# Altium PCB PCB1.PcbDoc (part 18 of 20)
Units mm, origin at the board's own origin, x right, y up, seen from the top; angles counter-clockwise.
Board outline 294.51 x 138.18 mm, 12 copper layers (Top Layer 1 _Signal, L2_GND, L3_Signals, L4_GND, L5_POWER, L6_Signals, L7_GND, L8_Signals, L9_GND, L10_POWER, L11_GND, Bottom Layer_Signals), stack 1.788 mm thick; 1254 components, 836 nets, 5699 pads, 2073 vias.
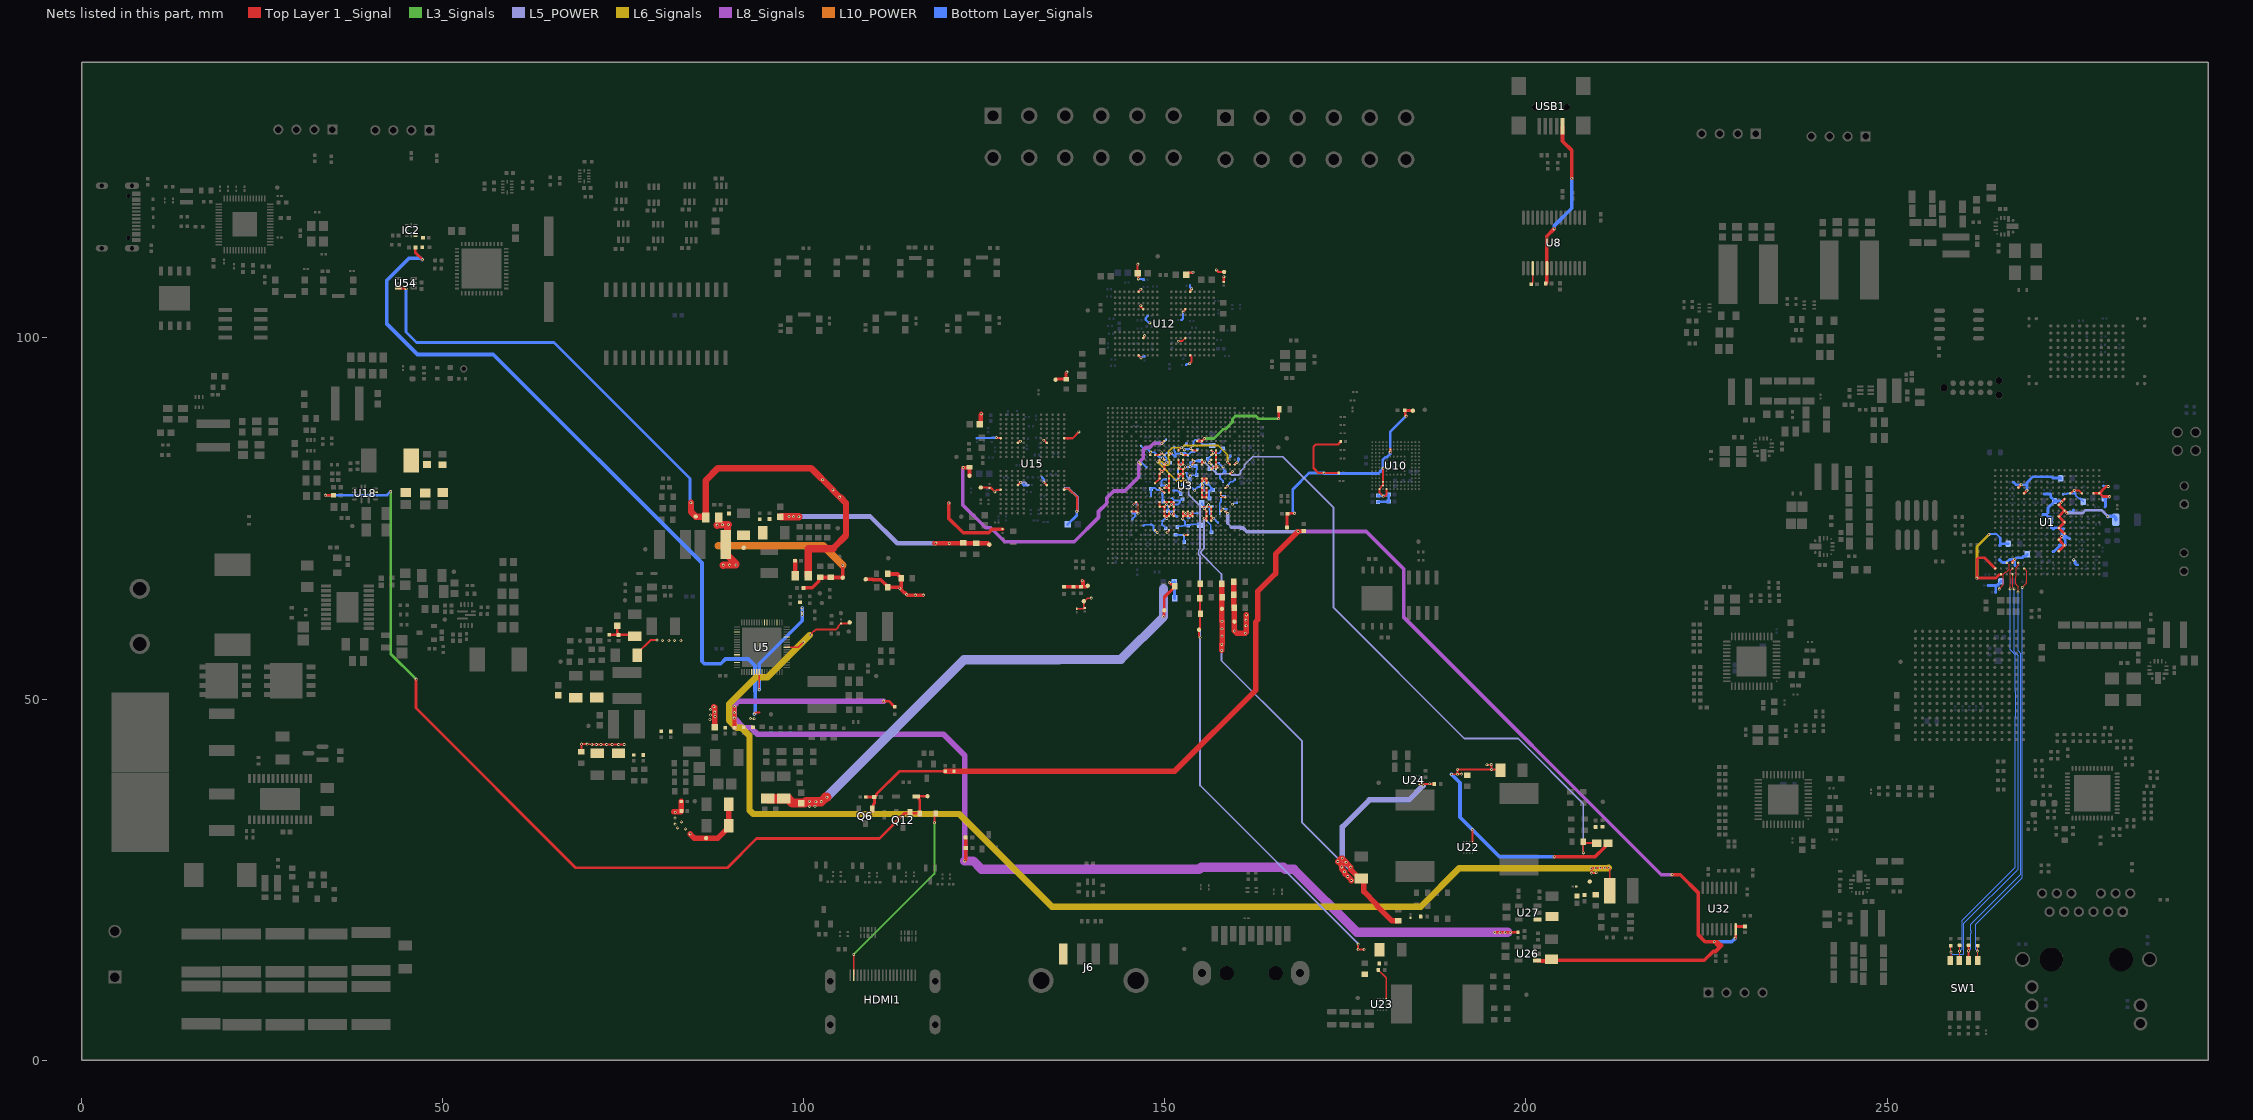
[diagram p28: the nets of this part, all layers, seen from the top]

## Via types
v1: diameter 0.4, hole 0.2, Top Layer 1 _Signal to Bottom Layer_Signals, 2009 vias
v2: diameter 0.508, hole 0.254, Top Layer 1 _Signal to Bottom Layer_Signals, 36 vias
v3: diameter 0.5, hole 0.2, Top Layer 1 _Signal to Bottom Layer_Signals, 12 vias
v4: diameter 1.27, hole 0.711, Top Layer 1 _Signal to Bottom Layer_Signals, 6 vias
v5: diameter 0.3, hole 0.2, Top Layer 1 _Signal to Bottom Layer_Signals, 5 vias
v6: diameter 0.254, hole 0.2, Top Layer 1 _Signal to Bottom Layer_Signals, 3 vias
v7: diameter 0.305, hole 0.2, Top Layer 1 _Signal to Bottom Layer_Signals, 1 vias
v8: diameter 0.254, hole 0.152, Top Layer 1 _Signal to Bottom Layer_Signals, 1 vias

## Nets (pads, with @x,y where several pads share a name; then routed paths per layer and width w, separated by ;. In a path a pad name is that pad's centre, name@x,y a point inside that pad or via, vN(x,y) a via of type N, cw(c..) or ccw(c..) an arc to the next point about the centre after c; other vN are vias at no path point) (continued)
VCC1V8_PMU_DDR_S3: C5.1 C315.1 C316.1 C317.1 C318.1 C319.1 C320.1 C322.1 C323.1 C324.1 C393.1 C394.1 C395.1 C396.1 C397.1 C398.1 C399.1 C400.1 C401.1 R30.1 R31.1 TP18.1 TP62.1 TP81.1 U3.N28 U3.R27 U12.F1 U12.F12 U12.G4 U12.G9 U12.T4 U12.T9 U12.U1 U12.U12 U15.F1 U15.F12 U15.G4 U15.G9 U15.T4 U15.T9 U15.U1 U15.U12 U54.6 | length 158.4
  Top Layer 1 _Signal w0.127: v1(147.207,100.311) v1@147.259,100.363
  Top Layer 1 _Signal w0.254: v1(151.854,99.547) 151.882,99.575 152.427,99.575 152.841,99.989 U12.T4@152.854,99.989
  Top Layer 1 _Signal w0.305: TP62.1@124.514,79.282 125.864,79.282 v1(126.463,78.683) 126.741,78.962 127.241,78.962 U15.F12@127.25,78.971 ; v1(126.67,86.192) 126.733,86.129 127.241,86.129 U15.U12@127.25,86.121 ; U15.G9@129.65,79.621 129.65,79.633 v1@130.02,80.003 ; U15.T9@129.65,85.471 129.662,85.471 129.879,85.688 v1(129.99,85.688) ; v1@130.012,80.033 v1(130.031,80.015) v1@130.02,80.004 ; v1(133.232,85.838) 133.25,85.82 133.301,85.82 U15.T4@133.65,85.471 ; v1(133.259,80.03) 133.259,80.021 133.65,79.63 U15.G4@133.65,79.621 ; U15.U1@136.05,86.121 137.229,86.121 v1(138.091,86.983) ; U15.F1@136.062,78.971 136.226,79.134 136.663,79.134 137.867,77.93 137.867,76.215 137.835,76.182 137.835,75.979 v1(137.817,75.961) ; v1(146.26,110.221) 146.26,110.196 146.229,110.164 146.229,108.931 C316.1@146.22,108.922 146.304,108.837 146.304,108.19 v1(146.322,108.172) ; U12.F1@146.354,97.589 146.354,97.577 v1(146.694,97.237) ; U12.F12@146.354,106.389 146.354,106.401 146.68,106.727 v1(146.68,106.745) ; v1(146.675,104.454) 146.675,104.331 147.004,104.001 U12.G9@147.004,103.989 ; U12.G4@147.004,99.989 147.004,100.001 147.144,100.141 147.144,100.223 147.207,100.285 v1(147.207,100.311) ; v1(152.52,103.585) 152.52,103.611 152.799,103.89 152.799,103.989 U12.T9@152.854,103.989 ; C315.1@152.941,108.747 153.233,109.039 153.848,109.039 v1(153.899,109.089) ; v1(153.417,96.425) 153.417,96.45 153.705,96.738 153.705,97.388 U12.U1@153.504,97.589 ; U12.U12@153.504,106.389 153.504,106.58 v1(153.716,106.792) ; v1(157.113,109.426) 157.138,109.426 157.43,109.134 TP81.1@158.201,109.134 ; C322.1@158.155,107.763 158.155,108.446 v1(158.174,108.465) ; U3.R27@159.029,81.178 159.029,81.182 159.349,81.502 159.349,81.52 v1(159.354,81.526) v1@159.354,81.582 ; U3.N28@159.679,82.478 159.683,82.478 159.967,82.761 v1(159.986,82.761)
  Top Layer 1 _Signal w0.381: U54.6@43.815,106.909 44.668,106.909 44.76,106.818 v1(44.924,106.818)
  Top Layer 1 _Signal w0.508: v1(120.092,77.141) 120.092,74.994 122.07,73.016 125.597,73.016 126.111,73.53 C401.1@127.508,73.53
  Top Layer 1 _Signal w0.635: C393.1@124.349,88.018 124.482,88.151 124.482,89.37 v1(124.591,89.479)
  Top Layer 1 _Signal w0.889: v1(84.38,77.182) 84.38,75.913 TP18.1@85.031,75.262 86.349,75.262 86.409,75.202 R31.1@86.409,75.116 86.409,80.26 88.126,81.977 101.001,81.977 104.022,78.956 v1(104.027,78.956) 104.027,78.906 v1(104.982,77.951) ; 104.078,70.871 105.851,72.645 105.851,77.127 v1@105.005,77.974
  Top Layer 1 _Signal w1.016: R30.1@100.622,67.063 100.622,67.232 100.626,67.236 100.626,70.818 104.024,70.818 104.078,70.871
  L5_POWER w0.305: v1(130.031,80.015) 130.049,79.997 130.638,79.997 131.024,79.61 ; v1@159.961,82.761 v1(159.986,82.761)
  L5_POWER w0.381: 136.007,79.041 136.138,79.172 136.684,79.172 137.906,77.95 137.906,76.199 137.821,76.114 137.821,75.964 v1(137.817,75.961)
  Bottom Layer_Signals w0.254: v1(146.694,97.237) 146.734,97.237 146.89,97.393 147.157,97.393 C324.1@147.17,97.406
  Bottom Layer_Signals w0.305: C398.1@123.965,86.114 123.993,86.142 124.952,86.142 124.962,86.132 C397.1@124.967,86.132 124.986,86.151 C399.1@126.034,86.151 ; C399.1@126.026,86.142 126.057,86.174 126.652,86.174 v1(126.67,86.192) ; v1(130.031,80.015) 130.057,80.015 130.466,79.605 131.064,79.605 C400.1@131.083,79.624 ; C396.1@133.009,80.685 133.241,80.454 133.241,80.049 v1(133.259,80.03) ; v1(146.322,108.172) 146.331,108.163 146.979,108.163 C323.1@147.077,108.066 ; C318.1@147.624,103.027 147.365,102.768 147.365,102.515 147.787,102.093 147.908,102.093 v1(147.926,102.075) ; C319.1@152.322,102.479 152.52,102.677 v1(152.52,103.585) ; C317.1@152.924,96.255 153.076,96.407 153.399,96.407 v1(153.417,96.425) ; C320.1@153.493,107.235 153.493,107.04 153.716,106.818 v1(153.716,106.792) ; v1(159.986,82.761) 159.986,82.787 160.174,82.974 160.174,83.259 C5.1@160.195,83.28
  Bottom Layer_Signals w0.381: v1(44.924,106.818) 44.924,100.828 46.377,99.376 65.401,99.376 84.261,80.516 84.261,77.306 84.38,77.187 v1(84.38,77.182) ; C394.1@136.545,74.178 137.814,75.447 137.814,75.957 v1(137.817,75.961)
  other v1: 102.614,80.365
VCC3V3_FT232: C545.1 U8.17 | length 2.3
  Top Layer 1 _Signal w0.254: C545.1@200.737,107.448 200.941,107.652 U8.17@200.941,109.664
VCC3V3_LCD: 6.2 U27.1
VCC5V0_FT232: C541.1 U8.20 USB1.1 | length 23.8
  Top Layer 1 _Signal w0.508: C541.1@202.752,107.534 202.891,107.673 U8.20@202.891,109.664 202.891,114.091 v1(203.899,115.098) ; USB1.1@205.058,129.303 205.058,127.244 206.364,125.937 206.364,122.119 v1(206.349,122.104)
  Bottom Layer_Signals w0.508: v1(203.899,115.098) 203.899,115.504 206.349,117.954 v1(206.349,122.104)
VCC5V0_USB20_HOST: J6.1
VCC5V_HDMI_TX0: D4.1 HDMI1.18 | length 27.1
  Top Layer 1 _Signal w0.254: HDMI1.18@106.925,11.745 v1(106.925,14.632) ; v1(118.082,32.866) 118.082,33.447 118.101,33.467 118.101,33.942 D4.1@118.289,34.13
  L3_Signals w0.254: v1(106.925,14.632) 118.082,25.789 v1(118.082,32.866)
VCC14: C176.2 C517.2 C518.1 C519.1 L22.2 R125.1 TP38.1 TP76.1 U5.9 | length 174.2
  Top Layer 1 _Signal w0.254: U5.9@97.644,57.17 99.225,57.17 v1(99.937,57.883) ; v1@100.892,58.837 101.137,59.083 101.137,59.176 101.378,59.417 101.472,59.417 101.684,59.629 104.478,59.629 104.784,59.935 104.784,60.097 105.156,60.469 C176.2@105.166,60.469 106.12,60.469 106.261,60.61 TP38.1@106.354,60.61 ; v1(209.718,25.938) 209.699,25.919 209.101,25.919 v1(209.082,25.9) 209.061,25.921 209.061,26.55 v1(209.039,26.571) 209.053,26.585 209.639,26.585 v1(209.653,26.598) 209.67,26.615 210.257,26.615 v1(210.274,26.633) 210.276,26.635 210.893,26.635 v1(210.895,26.637) 210.902,26.643 211.479,26.643 v1(211.485,26.65) 211.485,26.611 211.609,26.488 L22.2@211.609,23.452
  L6_Signals w0.889: v1@100.822,58.865 99.888,57.931 94.979,53.022 93.392,53.022 89.643,49.273 89.643,47.063 90.711,45.995 91.419,45.995 92.487,44.928 92.487,34.594 93.008,34.074 121.543,34.074 134.365,21.252 185.431,21.252 190.768,26.589 209.039,26.589 209.653,26.589 210.274,26.589 210.895,26.589 211.424,26.589 v1(211.485,26.65)
  other v1: 100.92,58.865
VCC_1V8_S0: C15.1 C32.1 C34.1 C203.1 C466.1 C467.1 C468.1 C556.2 C632.1 R100.2 R102.2 R133.2 R253.2 U3.AA7 U3.AC6 U3.AC7 U3.AC25 U3.H20 U3.H21 U3.W25 U3.Y26 U5.58 | length 189.9
  Top Layer 1 _Signal w0.152: U3.AA7@146.029,77.278 146.349,76.958 146.349,75.852 146.288,75.79 v1(146.288,75.723)
  Top Layer 1 _Signal w0.254: U3.AC6@145.379,75.978 146.033,75.978 v1(146.288,75.723) ; v5(145.676,76.939) 145.683,76.939 146.022,77.278 U3.AA7@146.029,77.278 ; U3.AC25@157.729,75.978 157.729,75.996 158.021,76.288 158.021,76.293 v1(158.025,76.297) ; U3.W25@157.729,78.578 157.742,78.565 157.742,78.049 v1(157.752,78.04) 157.791,78.04 157.89,77.941 158.367,77.941 U3.Y26@158.379,77.928
  Top Layer 1 _Signal w0.381: v1@111,49.632 111.071,49.702 v1(111.071,49.708) 111.075,49.704 111.79,49.704 112.526,48.968 112.526,48.849 C467.1@112.586,48.908 ; U3.H20@154.479,85.728 U3.H21@155.129,85.728 155.462,86.061 v1(155.462,86.064) v1@155.471,86.072 ; v1(165.756,88.821) 165.76,88.825 165.76,90.022 R253.2@165.835,90.097 ; v1(195.675,17.693) v1(196.432,17.693) v1(197.123,17.693) v1(197.839,17.693) R133.2@198.883,17.693
  Top Layer 1 _Signal w0.508: v1(90.4,48.938) 90.412,48.926 C556.2@90.412,46.032 ; v1(122.268,27.584) 122.419,27.735 R100.2@122.419,30.84
  L3_Signals w0.381: v1(155.462,86.064) 156.777,86.064 158.06,87.347 158.365,87.347 159.35,88.332 159.35,88.761 159.761,89.173 162.58,89.173 162.932,88.821 v1(165.756,88.821)
  L8_Signals w0.762: v1(111.071,49.708) 90.968,49.708 90.372,49.111 v1(90.372,47.364) 91.748,45.988 92.709,45.988 93.575,45.122 104.697,45.122 104.712,45.136 105.262,45.136 105.277,45.122 119.342,45.122 122.29,42.174 122.29,27.606 v1(122.268,27.584)
  L8_Signals w1.27: v1(122.268,27.584) 123.446,27.584 124.601,26.43 154.757,26.43 155.031,26.704 166.406,26.704 166.68,26.43 167.868,26.43 176.605,17.693 v1(195.675,17.693) v1(196.432,17.693) v1(197.123,17.693) 197.488,17.693
  Bottom Layer_Signals w0.254: C203.1@145.508,74.907 145.508,74.952 145.872,75.316 145.872,75.566 146.028,75.723 v1(146.288,75.723) ; C32.1@145.525,75.724 145.525,75.747 145.53,75.751 v1@146.26,75.751 ; v5(145.676,76.939) 145.689,76.939 145.811,77.061 146.073,77.061 146.11,77.024 146.11,77.012 146.221,76.901 C632.1@146.267,76.901 ; C34.1@157.597,75.656 157.598,75.923 ; v1(158.025,76.297) 158.04,76.282 158.517,76.282 158.53,76.269 C466.1@158.53,76.267 158.53,76.277 158.517,76.29 158.404,76.29 158.368,76.326 158.094,76.326 158.091,76.324 157.998,76.324 157.998,76.31 157.913,76.224 157.899,76.224 157.598,75.923 ; C15.1@158.263,78.135 158.259,78.139 157.89,78.139 157.791,78.04 v1(157.752,78.04) 157.752,77.27 157.598,77.116 157.598,75.923 ; v1(159.354,76.976) 159.394,76.976 159.521,77.103 160.003,77.103 160.007,77.107 C468.1@160.007,77.153
  other v1: 90.39,48.116
VCC_1V8_S3_PLDO6: C174.1 R30.2 U5.20 | length 2.1
  Top Layer 1 _Signal w0.635: C174.1@98.8,69.141 98.818,69.123 R30.2@98.818,67.063
VCC_2V0_PLD0_S3: C637.1 R292.2 R293.2
VCC_2V0_PLDO_S3: C553.1 C554.1 U5.13 U5.59 | length 16.2
  Top Layer 1 _Signal w0.254: v1(93.838,51.3) 93.844,51.305 93.844,53.72 U5.59@93.849,53.725
  Bottom Layer_Signals w0.508: v1(93.838,51.3) 93.838,54.885 99.791,60.837 99.791,61.617 v1(99.795,61.621) 99.795,62.073 v1(99.793,62.075) 99.774,62.094 v1(99.774,62.611)
VCC_3V3_S0: 5.2 C204.1 C547.1 J5.2 Q6.1 R107.1 R113.1 R114.1 R119.2 U3.AC26 U26.1 U32.16 | length 223.1
  Top Layer 1 _Signal w0.254: U3.AC26@158.379,75.978 v1(158.69,75.668)
  Top Layer 1 _Signal w0.381: R107.1@108.564,36.447 108.577,36.434 109.771,36.434 R119.2@109.785,36.42 ; Q6.1@109.495,34.767 109.63,34.901 109.63,35.408 109.785,35.563 R119.2@109.785,36.42 ; R113.1@119.593,39.996 113.235,39.996 110.06,36.82 110.06,36.674 109.806,36.42 R119.2@109.785,36.42 ; v1(228.965,16.884) 228.965,16.889 229.067,16.99 229.067,17.392 229.062,17.397 U32.16@229.062,17.435 ; U32.16@229.062,18.497 C547.1@230.328,18.497
  Top Layer 1 _Signal w0.508: v1(168.454,73.196) 168.492,73.234 169.216,73.234 J5.2@169.237,73.255 ; U26.1@201.553,13.791 201.599,13.745 202.09,13.745 202.123,13.711 203.31,13.711 5.2@203.551,13.953 203.38,13.953 5.2@203.036,13.609 ; 5.2@203.676,13.828 224.706,13.828 225.926,15.047 226.264,15.047 227.077,15.861 ; v1(220.245,25.67) 221.359,25.67 223.88,23.149 223.88,17.308 224.807,16.381 226.077,16.381 226.598,15.861 227.077,15.861 ; v1(226.081,16.385) 226.559,16.385 227.077,15.866 227.077,15.861
  Top Layer 1 _Signal w0.762: R113.1@119.593,39.996 120.813,39.996 151.359,39.996 162.552,51.189 162.552,60.66 162.857,60.966 162.857,64.912 165.325,67.38 165.325,70.067 v1(168.454,73.196)
  L5_POWER w0.254: 158.69,74.323 159.207,73.805
  L5_POWER w0.508: 158.69,74.323 v1(158.69,75.668) ; 159.207,73.805 160.419,73.805 160.532,73.692 160.819,73.692 161.346,73.165 168.205,73.165 168.236,73.196 v1(168.454,73.196)
  L8_Signals w0.508: v1(168.454,73.196) 177.872,73.196 183.102,67.966 183.102,61.288 218.72,25.67 v1(220.245,25.67)
  Bottom Layer_Signals w0.254: C204.1@158.681,74.754 158.685,74.758 158.685,75.664 v1(158.69,75.668)
  Bottom Layer_Signals w0.508: v1(226.081,16.385) 228.513,16.385 v1@228.965,16.837
VCC_5V0: C196.2 C197.2 C440.1 C441.1 C443.1 D4.2 D7.1 L16.2 Q12.1 R77.1 TP20.1 U18.5 | length 128.2
  Top Layer 1 _Signal w0.381: v1(33.748,78.224) 33.75,78.227 R77.1@34.877,78.227 ; v1(46.31,52.746) 46.31,48.741 68.426,26.625 89.4,26.625 93.469,30.693 110.461,30.693 113.956,34.188 116.001,34.188 D4.2@116.059,34.13 116.059,36.029 115.909,36.18 115.909,36.43 115.824,36.514 D7.1@115.574,36.514 115.59,36.53 117.127,36.53 TP20.1@117.143,36.546
  L3_Signals w0.381: v1(42.804,78.717) 42.804,56.251 v1(46.31,52.746)
  Bottom Layer_Signals w0.381: v1(33.748,78.224) 42.311,78.224 v1(42.804,78.717)
VCCA_1V8: C16.2 C305.2 C310.2 C455.2 C461.1 C462.2 C555.2 C683.1 C685.1 IC2.1 R128.2 R130.1 R273.1 TP61.1 U3.AG11 U3.AG14 U3.AH18 U3.K16 U3.M12 U3.N27 U3.U18 U5.60 | length 133.2
  Top Layer 1 _Signal w0.254: v1(93.145,47.916) 93.377,48.148 93.878,48.148 ; C16.2@137.804,62.509 138.774,62.509 138.885,62.62 C305.2@138.885,62.646 ; C305.2@138.908,62.633 138.898,62.633 C305.2@138.885,62.646 ; v1(139.808,63.981) 139.78,63.953 139.284,63.953 138.871,63.54 TP61.1@138.778,63.54 138.778,62.763 138.885,62.656 C305.2@138.885,62.646 ; U3.AG11@148.629,73.378 v1(148.94,73.067) ; v1(149.015,82.834) 149.015,82.864 U3.M12@149.279,83.128 ; v1(150.305,73.083) 150.305,73.085 150.579,73.36 U3.AG14@150.579,73.378 ; U3.K16@151.879,84.428 152.243,84.792 v1(152.297,84.792) v1@152.297,84.777 ; v1(152.66,72.728) U3.AH18@153.179,72.728 ; v1(152.895,80.17) 152.895,80.166 153.179,79.882 U3.U18@153.179,79.878 ; v1@158.677,82.803 v1(158.682,82.803) 158.686,82.803 159.011,82.478 U3.N27@159.029,82.478
  Top Layer 1 _Signal w0.381: R273.1@46.203,112.527 46.203,111.828 v1(47.188,110.843)
  L6_Signals w0.254: v1(152.895,80.17) 151.68,80.17 149.016,82.834 149.043,82.862 149.591,82.862 150.081,82.372 150.425,82.372 150.665,82.612 150.665,83.09 150.484,83.271 150.484,84.24 151.036,84.792 152.337,84.792 152.65,85.104 157.396,85.104 158.672,83.828 158.672,82.812 v1(158.682,82.803)
  Bottom Layer_Signals w0.254: C310.2@147.065,74.022 147.075,74.022 147.19,74.138 C462.2@148.087,74.138 148.1,74.125 148.268,74.125 148.418,73.974 148.418,73.443 148.766,73.095 148.912,73.095 v1(148.94,73.067) ; R128.2@151.489,72.747 152.048,72.747 152.077,72.719 152.651,72.719 v1(152.66,72.728) 152.667,72.721 152.667,71.754 R130.1@152.673,71.747 ; v1(152.297,84.792) 152.325,84.819 152.408,84.819 152.95,85.362 C461.1@152.996,85.362 ; v1(158.682,82.803) 158.71,82.831 158.71,83.226 159.086,83.602 C455.2@159.086,83.648
  Bottom Layer_Signals w0.508: v1(47.188,110.843) 46.974,111.056 45.359,111.056 42.234,107.93 42.234,102.002 46.522,97.713 57.012,97.713 85.899,68.826 85.899,55.214 86.214,54.899 88.51,54.899 89.148,55.537 92.311,55.537 93.247,54.601 93.247,51.054 93.301,51 93.301,48.072 v1(93.145,47.916)
  other v1: 93.115,47.273 92.599,47.288
VCCQ: C63.1 C64.1 C210.2 C211.2 C212.1 C213.2 C214.2 C215.2 L4.1 R31.2 R41.2 R65.1 R66.2 R67.1 R172.2 TP39.1 TP43.1 TP45.1 U3.V26 U5.25 U10.C6 U10.M4 U10.N4 U10.P3 U10.P5 | length 90
  Top Layer 1 _Signal w0.203: U10.P3@179.704,79.07 U10.N4@180.204,79.57
  Top Layer 1 _Signal w0.254: U3.V26@158.379,79.228 158.379,79.245 158.384,79.241 158.41,79.241 158.649,79.48 v1(158.655,79.48)
  Top Layer 1 _Signal w0.305: R67.1@174.064,81.322 174.064,81.302 174.042,81.279 171.281,81.279 170.579,81.982 170.579,84.926 170.896,85.243 173.968,85.243 174.316,85.592 174.341,85.592 174.364,85.614 R65.1@174.364,85.639 ; U10.P3@179.704,79.07 179.704,78.612 v1(180.23,78.085) 180.248,78.104 180.518,78.104 180.704,78.289 U10.P5@180.704,79.07 ; U10.N4@180.204,79.57 U10.M4@180.204,80.07 180.204,80.989 180.222,81.007 v1(180.222,81.952)
  Top Layer 1 _Signal w0.381: TP45.1@166.915,73.748 166.915,75.379 167.252,75.717 v1(167.961,75.717) ; R66.2@166.975,75.652 R66.2@167.252,75.652 ; v1(181.195,84.181) 181.199,84.184 181.199,84.565 U10.C6@181.204,84.57 ; v1(183.416,89.176) 183.416,89.181 183.275,89.321 183.275,89.901 C212.1@183.216,89.96 183.236,89.941 184.318,89.941 TP43.1@184.338,89.921
  Top Layer 1 _Signal w0.508: R41.2@99.957,65.403 101.163,65.403 102.081,66.321 102.081,66.712 102.202,66.833 105.347,66.833 105.378,66.802 TP39.1@105.403,66.802 v1(105.403,68.51)
  Top Layer 1 _Signal w1.016: v1(87.989,74.081) 88.045,74.137 v1(88.735,74.137) 88.767,74.169 v1(89.553,74.169) 89.449,74.066 89.449,71.647 L4.1@89.207,71.405 89.207,70.155 90.62,68.742 v1(90.62,68.554) 89.746,68.554 v1(89.738,68.546) 88.863,68.546 v1(88.855,68.538)
  L10_POWER w1.016: 88.122,71.223 102.69,71.223 v1(105.403,68.51)
  Bottom Layer_Signals w0.203: v1(158.655,79.48) 158.693,79.517 158.693,79.629 159.122,80.059 159.382,80.059 159.513,80.19 159.513,80.202 159.695,80.384 C215.2@159.695,80.394
  Bottom Layer_Signals w0.305: C211.2@179.539,78.155 179.59,78.104 180.212,78.104 v1(180.23,78.085) 180.256,78.085 180.349,78.179 180.893,78.179 C213.2@181.011,78.296
  Bottom Layer_Signals w0.381: v1(167.961,75.717) 167.961,75.722 167.711,75.972 167.711,79.017 169.982,81.287 v1(172.048,81.287) 172.054,81.287 172.127,81.214 179.599,81.214 179.868,81.484 179.868,81.593 180.222,81.946 v1(180.222,81.952) 180.218,81.955 180.218,82.329 180.197,82.35 180.197,83.164 180.524,83.491 180.775,83.491 181.191,83.908 181.191,84.177 v1(181.195,84.181) 181.195,87.001 183.37,89.176 v1(183.416,89.176) ; C214.2@179.525,77.284 179.562,77.32 180.966,77.32 C210.2@181.002,77.357 181.007,77.361 181.007,78.292 C213.2@181.011,78.296
VCORE0: R16.2 SW1.1 U1.P18 | length 58.3
  Top Layer 1 _Signal w0.132: SW1.1@262.551,13.773 262.547,13.777 v1(262.547,15.086) 262.559,15.098 262.559,15.85 R16.2@262.571,15.862 ; v1(268.717,65.455) 269.371,66.109 269.371,67.69 U1.P18@268.981,68.08
  Bottom Layer_Signals w0.132: v1(262.547,15.086) 262.262,15.371 262.262,18.827 268.717,25.282 v1(268.717,65.455)
VCORE1: R17.2 SW1.2 U1.R17 | length 59.3
  Top Layer 1 _Signal w0.132: v1(268.137,64.803) 268.137,65.56 267.866,65.831 267.866,65.864 267.801,65.929 267.801,66.943 267.866,67.009 267.866,68.21 268.173,68.517 268.173,68.872 U1.R17@268.181,68.88
  Top Layer 1 _Signal w0.305: SW1.2@261.281,13.773 v1(261.281,15.113) 261.285,15.116 261.285,15.882 R17.2@261.289,15.885
  Bottom Layer_Signals w0.132: v1(261.281,15.113) 261.601,15.432 261.601,17.533 261.633,17.565 261.633,17.855 261.601,17.887 261.601,18.832 268.501,25.733 268.501,56.294 268.137,56.658 v1(268.137,64.803)
VCORE2: R18.2 SW1.3 U1.T18 | length 58.8
  Top Layer 1 _Signal w0.132: SW1.3@260.011,13.773 260.036,13.797 v1(260.036,15.072) 260.039,15.074 260.039,15.883 R18.2@260.041,15.885 ; v1(267.052,65.253) 267.052,67.751 U1.T18@267.381,68.08
  Bottom Layer_Signals w0.132: v1(260.036,15.072) 260.386,15.421 260.386,19.361 267.735,26.71 267.735,47.643 267.789,47.697 267.789,51.024 267.735,51.078 267.735,56.108 267.052,56.792 v1(267.052,65.253)
VCORE3: R19.2 SW1.4 U1.T19 | length 60.1
  Top Layer 1 _Signal w0.132: SW1.4@258.741,13.773 258.858,13.89 v1(258.858,14.965) 258.838,14.985 258.838,15.83 R19.2@258.818,15.85 ; U1.T19@267.381,67.28 267.381,65.475 v1(267.598,65.257)
  Bottom Layer_Signals w0.132: v1(258.858,14.965) 258.909,14.914 258.909,14.781 259.018,14.672 260.545,14.672 260.622,14.749 260.622,18.921 268.145,26.444 268.145,56.004 267.598,56.55 v1(267.598,65.257)
VDD2_DDR_CKE: C295.2 C299.2 R264.1 TP56.1 U3.H13 U3.N8 | length 48.6
  Top Layer 1 _Signal w0.203: v1@146.39,82.755 v1(146.41,82.775) 146.414,82.775 146.679,82.51 U3.N8@146.679,82.478 ; v1@149.443,85.403 v1(149.582,85.403) 149.597,85.403 149.922,85.728 U3.H13@149.929,85.728
  Top Layer 1 _Signal w0.508: v1(122.077,82.039) 122.048,82.01 R264.1@122.852,82.01 ; R264.1@122.927,82.085 R264.1@122.852,82.01 ; TP56.1@122.957,80.905 122.942,80.92 122.942,82.01 R264.1@122.852,82.01
  L8_Signals w0.508: v1(122.077,82.039) 122.026,81.988 122.026,76.87 125.182,73.713 125.893,73.713 127.832,71.775 137.446,71.775 140.82,75.149 140.82,75.965 141.945,77.089 141.945,77.845 142.272,78.171 142.296,78.171 142.936,78.811 144.445,78.811 146.379,80.745 v1@146.379,82.744 ; v1(146.41,82.775) 146.541,82.906 146.577,82.906 146.995,83.325 146.995,84.534 147.292,84.832 147.9,84.832 148.472,85.403 v1(149.582,85.403)
  Bottom Layer_Signals w0.203: v1(146.41,82.775) 146.718,82.775 147.348,82.145 147.433,82.145 147.433,82.135 C299.2@147.471,82.096 ; v1(149.582,85.403) 149.619,85.441 149.752,85.441 149.921,85.609 149.921,85.694 150.128,85.902 C295.2@150.128,85.912
VDD_CPU_BIG0_S0: C38.1 C260.2 C261.1 C271.2 C272.2 C273.1 C274.1 C276.1 C277.2 C278.2 C279.1 C280.1 C506.1 C507.1 R121.1 R308.2 TP54.1 U3.M16 U3.M17 U3.M19 U3.N16 U3.N17 U3.N19 U3.P16 U3.P17 U3.R16 U3.R17 U3.T16 U3.T17 U23.A4 | length 105.6
  Top Layer 1 _Signal w0.254: U3.T16@151.879,80.528 U3.R16@151.879,81.178 U3.R17@152.529,81.178 ; U3.M16@151.879,83.128 U3.N16@151.879,82.478 U3.N17@152.529,82.478 152.529,83.11 152.511,83.128 U3.M17@152.529,83.128 ; v1(151.996,82.144) 151.892,82.04 151.892,81.841 U3.P16@151.879,81.828 U3.P17@152.529,81.828 ; U3.T17@152.529,80.528 U3.R17@152.529,81.178 ; v1(152.855,82.137) 152.547,81.828 U3.P17@152.529,81.828 ; U3.N19@153.829,82.478 153.829,82.496 153.988,82.655 153.988,82.895 v1(154.016,82.923) 154.016,82.932 153.829,83.119 U3.M19@153.829,83.128 ; v1(154.876,58.499) 154.876,58.539 154.732,58.683 154.732,59.454 154.869,59.591 154.889,59.591 C38.1@154.889,65.947 ; v1(176.76,16.052) 176.757,16.049 176.757,15.308 v1(176.753,15.304) 176.757,15.301 177.588,15.301 v1(177.591,15.298) 177.597,15.298 177.61,15.285 v1@177.623,15.285 ; C507.1@179.558,12.503 179.558,12.478 180.653,11.384 U23.A4@180.653,8.514 ; U3.R17@152.529,81.178 U3.P17@152.529,81.828
  L5_POWER w0.254: v1(153.517,80.863) 153.255,80.601 153.255,80.39 153.305,80.34 153.305,78.284 154.876,76.713 154.876,70.785 154.688,70.597 154.688,69.977 154.876,69.789 v1(154.876,58.499) 154.876,38.027 v1@176.805,16.098
  Bottom Layer_Signals w0.254: C278.2@151.283,80.401 151.296,80.388 151.531,80.388 151.599,80.32 152.123,80.844 v5(152.123,80.875) ; C260.2@151.836,81.308 151.836,81.945 151.968,82.077 151.968,82.116 v1@152.024,82.172 ; v1(151.996,82.144) 151.996,82.172 152.296,82.472 152.296,82.616 152.3,82.62 C279.1@152.346,82.62 ; v1(152.855,82.137) 152.867,82.149 153.478,82.149 v1(153.49,82.161) ; C261.1@152.992,81.327 153.038,81.327 153.042,81.323 153.042,80.836 153.097,80.781 153.097,80.767 153.507,80.357 153.58,80.284 C280.1@153.58,80.238 ; C280.1@153.56,80.41 153.56,80.78 153.517,80.823 v1(153.517,80.863) 153.556,80.863 153.679,80.985 154.343,80.985 C276.1@154.343,81.02 ; 154.342,81.49 154.342,81.67 154.469,81.797 C271.2@154.469,82.168 ; 154.343,81.49 154.343,81.104 C276.1@154.422,81.025 ; C271.2@154.386,82.168 154.37,82.168 C271.2@154.274,82.264 154.199,82.189 153.518,82.189 v1(153.49,82.161) ; C276.1@154.422,81.064 C276.1@154.442,81.044 ; C272.2@154.795,83.01 154.736,82.951 154.044,82.951 v1(154.016,82.923) 153.977,82.923 153.847,82.792 153.538,82.792 153.525,82.779 C277.2@153.525,82.77 153.512,82.757 153.512,82.183 v1(153.49,82.161)
VDD_CPU_BIG1_MEM_S0: C508.1 FB9.2 U3.M21 U3.N21 | length 94.2
  Top Layer 1 _Signal w0.254: U3.N21@155.129,82.478 U3.M21@155.129,83.128 ; U3.N21@155.152,82.478 155.145,82.485 155.145,82.505 155.453,82.813 v1(155.453,82.825) ; v1(207.943,28.69) 207.932,28.701 207.932,30.251 C508.1@207.922,30.262 208.138,30.046 FB9.2@209.811,30.046
  L5_POWER w0.254: v1(155.453,82.825) 156.334,81.944 156.41,81.944 157.174,81.18 158.007,81.18 158.026,81.199 159.038,81.199 159.232,81.005 160.244,81.005 160.485,81.245 160.485,81.576 161.029,82.12 161.029,82.416 162.167,83.554 166.307,83.554 173.372,76.489 173.372,62.626 191.467,44.532 198.929,44.532 207.943,35.518 v1(207.943,28.69)
VDD_CPU_BIG1_S0: C37.1 C251.2 C252.2 C253.1 C254.1 C255.1 C256.2 C257.2 C258.1 C259.1 C498.1 C499.1 FB9.1 R120.1 R307.2 TP52.1 U3.K23 U3.K24 U3.L23 U3.L24 U3.M23 U3.M24 U3.N23 U3.N24 U3.P23 U3.P24 U22.A4 | length 68.2
  Top Layer 1 _Signal w0.254: U3.P23@156.429,81.828 156.447,81.828 156.706,82.087 156.792,82.087 v1(156.82,82.115) ; U3.N23@156.429,82.478 156.412,82.478 156.164,82.726 v1(156.147,82.726) 156.147,82.846 U3.M23@156.429,83.128 ; U3.L23@156.429,83.778 156.429,83.796 156.696,84.063 v1(156.696,84.083) 156.696,84.143 156.429,84.41 U3.K23@156.429,84.428 ; U3.P24@157.079,81.828 U3.N24@157.079,82.478 ; U3.K24@157.079,84.428 U3.L24@157.079,83.778 U3.M24@157.079,83.128 U3.N24@157.079,82.478 ; v1(157.365,82.136) 157.365,82.174 157.079,82.46 U3.N24@157.079,82.478 ; v1(189.701,39.584) 190.496,39.584 190.515,39.604 190.525,39.594 191.051,39.594 v1(191.06,39.604) ; v1(190.515,39.584) v1(190.515,40.257) v1(195.241,40.257) ; v1(192.572,31.926) 192.598,31.899 U22.A4@192.598,30.261 ; v1(194.6,40.899) 194.607,40.906 195.196,40.906 v1(195.202,40.912) 195.222,40.893 195.222,40.277 v1(195.241,40.257) ; R307.2@196.475,40.145 196.363,40.257 v1(195.241,40.257)
  Top Layer 1 _Signal w0.508: v1(203.917,28.152) 209.578,28.152 210.964,29.539 210.964,29.771 211.239,30.046 FB9.1@211.363,30.046
  Top Layer 1 _Signal w0.762: C37.1@159.563,66.27 159.563,62.724 159.593,62.694 C254.1@159.593,62.631 159.593,60.755 TP52.1@159.631,60.717 159.631,59.455 159.984,59.102 v1(161.126,59.102) 161.253,59.229 v1(161.253,60.138) v1(161.253,60.919) 161.253,61.616 v1(161.287,61.649)
  Bottom Layer_Signals w0.254: v1(156.147,82.726) v1@156.178,82.757 ; C251.2@156.155,81.845 156.278,81.968 156.674,81.968 v1(156.82,82.115) ; C256.2@157.186,81.152 157.176,81.152 157.163,81.165 157.163,81.3 157.043,81.42 157.043,81.796 157.365,82.118 v1(157.365,82.136) 157.354,82.125 156.831,82.125 v1(156.82,82.115) ; C257.2@157.46,82.659 157.47,82.659 157.949,82.181 158.049,82.181 158.105,82.125 158.105,81.802 158.376,81.532 158.376,81.44 158.371,81.436 158.138,81.436 157.855,81.153 157.796,81.153 157.648,81.004 157.648,80.553 158.056,80.145 C258.1@158.056,80.099 ; C252.2@158.068,84.698 158.043,84.698 157.704,84.359 157.704,84.218 157.524,84.039 156.844,84.039 156.828,84.055 156.724,84.055 v1(156.696,84.083) 156.668,84.055 156.668,83.971 C255.1@155.941,83.244 155.986,83.198 155.986,82.948 v1@156.178,82.757 ; v1@156.178,82.757 v1(156.82,82.115)
  Bottom Layer_Signals w0.508: v1(189.701,39.584) 190.871,38.415 190.871,33.627 v1(192.572,31.926) 196.345,28.152 v1(203.917,28.152)
  other v1: 159.668,59.418 158.077,82.153
VDD_CPU_LIT_S0: C36.1 C62.2 C220.2 C221.2 C222.1 C223.1 C224.1 C226.1 C228.1 C229.1 C442.1 R34.1 R286.2 R287.2 TP46.1 U3.T21 U3.T22 U3.U21 U3.U22 U3.V21 U3.V22 U3.W21 U3.W22 U3.Y21 U3.Y22 U5.37 | length 35.3
  Top Layer 1 _Signal w0.305: R34.1@73.057,58.91 76.373,58.91 R287.2@76.598,58.685 ; C442.1@74.177,60.15 74.177,59.243 74.237,59.183 74.237,58.972 C62.2@74.344,58.865 ; R286.2@76.947,56.079 76.947,56.329 78.793,58.175 79.677,58.175 v1(79.679,58.173) ; U3.V21@155.129,79.228 155.129,79.224 155.177,79.177 155.177,78.756 155.132,78.712 155.132,78.581 U3.W21@155.129,78.578 U3.Y21@155.129,77.928 U3.Y22@155.779,77.928 U3.W22@155.779,78.578 U3.V22@155.779,79.228 ; U3.V21@155.129,79.381 155.217,79.469 155.217,79.575 v1(155.235,79.593) 155.235,79.619 155.132,79.721 155.132,79.875 U3.U21@155.129,79.878 U3.T21@155.129,80.528 U3.T22@155.775,80.528 ; v1(155.433,80.202) 155.449,80.202 U3.T22@155.775,80.528 ; U3.U22@155.779,79.878 U3.T22@155.779,80.528 U3.T22@155.775,80.528
  Top Layer 1 _Signal w0.508: TP46.1@108.577,66.581 108.595,66.563 109.524,66.563 109.561,66.526 110.662,66.526 111.651,65.538 C224.1@111.651,65.463 113.175,65.463 v1(113.311,65.326) ; C223.1@111.626,67.314 112.971,67.314 113.48,66.805 C36.1@113.48,66.73 113.48,65.495 v1(113.311,65.326) ; v1(116.554,64.391) v1(115.454,64.391) 114.323,64.391 v1(114.246,64.467) 114.007,64.707 113.93,64.707 v1(113.311,65.326)
  Bottom Layer_Signals w0.305: C228.1@152.396,79.675 152.396,79.672 152.417,79.651 152.451,79.651 152.827,79.275 153.734,79.275 154.106,78.903 v1(154.132,78.903) 154.15,78.921 154.15,78.963 154.56,79.373 154.806,79.373 154.962,79.53 154.962,79.667 155.054,79.759 C226.1@155.058,79.759 ; C226.1@155.082,79.738 155.228,79.593 v1(155.235,79.593) 155.235,79.567 155.371,79.431 155.371,78.914 C229.1@155.43,78.854 ; v1(155.433,80.202) 155.451,80.183 155.451,80.013 155.656,79.808 155.9,79.808 C220.2@155.914,79.822 ; C220.2@155.993,79.719 156.582,79.13 156.582,79.105 156.679,79.008 C221.2@156.679,78.951 ; C222.1@156.187,77.769 156.118,77.838 156.118,78.741 156.381,79.003 156.491,79.003 C221.2@156.495,79.007
  other v1: 80.423,58.125 81.33,58.118 82.094,58.118 82.983,58.108
VDD_DDR_S0: C46.1 C51.2 C296.2 C297.1 C300.2 C301.1 C304.2 C306.1 C307.1 C309.2 C311.1 C312.1 R29.2 R148.2 R149.2 TP59.1 U3.L11 U3.L12 U3.L13 U3.L14 U3.L17 U3.L18 U3.N13 U3.P12 U3.P13 U3.R12 U3.T12 U3.U11 U5.46 | length 28.4
  Top Layer 1 _Signal w0.254: C46.1@69.211,42.676 69.219,42.684 v1(69.219,43.76) 69.226,43.753 69.984,43.753 v1(69.991,43.746) 70.005,43.732 70.639,43.732 v1(70.653,43.718) 70.66,43.711 71.267,43.711 v1(71.274,43.705) v1(71.908,43.705) v1(72.694,43.705) v1(73.453,43.705) v1(74.349,43.705) v1(75.135,43.705) ; U3.U11@148.629,79.878 U3.T12@149.279,80.528 U3.R12@149.279,81.178 149.285,81.178 v1(149.58,81.473) ; U3.L11@148.629,83.778 U3.L12@149.279,83.778 ; U3.P12@149.279,81.828 149.279,81.81 149.58,81.51 v1(149.58,81.473) ; U3.L12@149.297,83.778 U3.L12@149.279,83.778 ; U3.L13@149.929,83.778 149.911,83.778 149.597,84.093 v1(149.57,84.093) 149.553,84.075 149.553,84.069 149.279,83.796 U3.L12@149.279,83.778 ; v1(150.255,82.783) 150.244,82.783 149.955,82.493 149.932,82.493 149.929,82.496 U3.P13@149.929,81.828 149.929,81.825 149.58,81.476 v1(149.58,81.473) ; U3.L14@150.579,83.778 150.591,83.778 150.883,84.07 v1(150.895,84.07) v1@150.901,84.064 ; v1(152.27,84.022) 152.278,84.022 152.521,83.778 U3.L18@153.179,83.778
  Top Layer 1 _Signal w0.508: C311.1@136.036,65.541 136.063,65.569 C304.2@137.356,65.569 138.338,65.569 138.349,65.557 C309.2@138.366,65.557 138.666,65.557 ; v1(138.566,66.384) 138.666,66.283 138.666,65.557 ; TP59.1@139.321,65.684 139.296,65.684 139.169,65.557 138.666,65.557
  Bottom Layer_Signals w0.254: C307.1@149.553,82.622 150.054,82.622 150.215,82.783 v1(150.255,82.783) ; v1(149.57,84.093) 149.582,84.093 149.938,83.737 C301.1@150.03,83.737 ; C306.1@150.732,82.706 150.683,82.755 150.283,82.755 v1(150.255,82.783) ; C297.1@151.311,84.937 151.311,84.37 151.384,84.297 151.384,84.09 151.462,84.012 151.462,83.938 151.466,83.934 151.466,83.802 ; C296.2@154.535,84.6 154.525,84.6 154.144,84.219 153.628,84.219 153.213,83.804 153.213,83.714 C300.2@153.2,83.701 153.2,83.711 153.021,83.89 153.021,83.938 152.897,84.062 152.35,84.062 152.309,84.022 v1(152.27,84.022) 152.264,84.016 151.689,84.016 151.537,83.863 151.454,83.78 151.454,83.576 151.449,83.572 151.358,83.572 150.886,84.043 150.886,84.079 150.228,84.079 150.034,83.885 150.034,83.741 C301.1@150.03,83.737 ; C301.1@150.03,83.737 150.034,83.732 150.034,83.573 150.243,83.364 150.243,82.794 v1(150.255,82.783)
VDD_GPIO_S0: C45.2 R28.1 U5.49
VDD_GPU_S0: C18.1 C227.1 C232.2 C233.2 C237.1 C238.1 C239.1 C240.1 C241.1 C242.1 C350.1 R247.2 R248.2 TP48.1 U3.AA12 U3.AA13 U3.AA14 U3.AA15 U3.AB12 U3.AB13 U3.AB14 U3.AB15 U3.AC13 U3.AC14 U3.AC15 U3.AD13 U3.AD14 U3.AD15 | length 95.9
  Top Layer 1 _Signal w0.254: U3.AA12@149.279,77.278 U3.AB12@149.279,76.628 U3.AB13@149.929,76.628 U3.AC13@149.929,75.978 U3.AD13@149.929,75.328 ; U3.AB13@149.929,76.629 v1(150.253,76.953) ; U3.AA13@149.929,77.278 U3.AA14@150.579,77.278 U3.AA15@151.229,77.278 U3.AB15@151.229,76.628 U3.AC15@151.229,75.978 151.229,75.343 U3.AD15@151.215,75.328 ; U3.AD13@149.978,75.328 U3.AD13@149.929,75.328 ; v1(150.262,75) 150.26,75 149.932,75.328 U3.AD13@149.929,75.328 ; U3.AC14@150.579,75.978 U3.AD14@150.579,75.328 U3.AD13@149.929,75.328 ; U3.AB14@150.579,76.628 150.9,76.949 v1(150.905,76.949) ; v1(150.918,75.625) U3.AD15@151.215,75.328 ; U3.AD15@151.229,75.328 U3.AD15@151.215,75.328
  Top Layer 1 _Signal w0.381: v1(149.834,61.413) 149.876,61.455 149.876,62.239 TP48.1@149.918,62.281 149.918,64.088 151.377,65.547 C18.1@151.377,65.622 151.377,65.697 151.192,65.881 150.853,65.881 150.622,66.113 v1(150.617,66.113)
  Top Layer 1 _Signal w1.27: R247.2@95.01,36.219 95.05,36.179 97.84,36.179 98.43,35.588 C350.1@99.639,35.588 100.098,35.588 100.326,35.816 v1(100.785,35.816) 100.829,35.772 v1(101.673,35.772) ; v1@101.723,35.772 102.391,35.772 v1(102.413,35.794) 103.02,36.401 v1(103.191,36.401)
  L5_POWER w1.27: v1@103.191,36.439 122.178,55.427 135.38,55.427 135.441,55.488 143.909,55.488 v1(149.834,61.413) 149.834,65.268
  Bottom Layer_Signals w0.254: C233.2@150.112,73.648 150.112,73.673 149.757,74.028 149.757,74.061 149.645,74.061 149.645,74.107 149.598,74.107 149.598,74.192 149.632,74.225 149.632,74.633 C227.1@149.645,74.646 149.645,74.656 149.96,74.972 150.234,74.972 v1(150.262,75) ; v1(150.253,76.953) 150.253,76.914 150.467,76.7 150.467,76.042 C239.1@150.429,76.004 150.487,75.946 151.003,75.946 151.269,76.212 C241.1@151.315,76.212 ; v1(150.905,76.949) 150.933,76.921 151.762,76.921 152.112,77.271 152.112,77.464 152.181,77.533 ; v1(150.918,75.625) 150.946,75.597 151.291,75.597 151.623,75.265 151.633,75.265 C240.1@151.646,75.252 ; C242.1@150.974,77.797 151.019,77.797 151.346,77.471 151.843,77.471 151.906,77.533 152.181,77.533 ; C232.2@152.465,77.656 152.44,77.656 152.317,77.533 152.181,77.533
  Bottom Layer_Signals w0.381: v1(150.617,66.113) 150.62,66.117 151.239,66.117 C238.1@151.326,66.203 151.344,66.185 151.344,63.945 C237.1@151.363,63.926
  other v1: 100.818,35.137 101.552,35.148
VDD_LOG_S0: C157.2 C262.2 C263.2 C264.1 C265.1 C266.1 C267.1 C268.1 C269.1 C270.1 C444.1 R36.1 R288.2 R289.2 TP53.1 U3.AC17 U3.AC18 U3.AC19 U3.AD17 U3.AD18 U3.AD19 U3.K19 U3.K20 U3.V16 U3.V17 U5.56 | length 34.9
  Top Layer 1 _Signal w0.254: v1(152.452,74.947) 152.452,74.987 152.517,75.051 152.517,75.315 U3.AD17@152.529,75.328 ; U3.AC17@152.529,75.978 U3.AD17@152.529,75.328 ; v1(152.864,75.671) 152.864,75.667 152.529,75.332 U3.AD17@152.529,75.328 ; U3.AC18@153.179,75.978 U3.AD18@153.179,75.328 ; v1(153.463,75.657) 153.482,75.657 153.811,75.328 U3.AD19@153.829,75.328 ; v1(153.582,84.693) 153.829,84.446 U3.K19@153.829,84.428 U3.K20@154.479,84.428 U3.K20@154.479,84.41 ; U3.AC19@153.829,75.978 U3.AD19@153.829,75.328 ; U3.AD17@152.529,75.328 U3.AD18@153.179,75.328 ; U3.AD18@153.179,75.328 U3.AD19@153.829,75.328
  Top Layer 1 _Signal w0.305: U3.V16@151.879,79.228 151.879,79.218 151.906,79.218 U3.V16@151.913,79.225 ; v1(152.179,78.905) 152.179,78.931 151.913,79.197 U3.V16@151.913,79.225 ; U3.V17@152.529,79.228 152.526,79.225 U3.V16@151.913,79.225
  Top Layer 1 _Signal w0.762: 82.002,34.392 82.963,34.392 C157.2@83.061,34.49 ; C157.2@83.043,34.49 R36.1@83.043,35.814 ; v1(84.267,31.329) 84.267,31.306 84.832,30.741 TP53.1@86.472,30.741 88.113,30.741 89.595,32.224 R289.2@89.595,32.474 R288.2@89.595,35.428 ; v1(87.556,48.935) 87.64,48.851 C444.1@87.64,46.105
  Bottom Layer_Signals w0.089: v1(152.864,75.671) 152.867,75.668 152.867,75.337 153.216,74.989 153.237,75.01 153.316,75.01 153.412,75.105 C265.1@153.412,75.115
  Bottom Layer_Signals w0.254: C269.1@151.209,78.881 151.761,78.881 152.011,78.631 152.158,78.631 152.158,78.399 C263.2@152.181,78.376 ; C262.2@151.713,73.821 151.816,73.924 152.344,73.924 152.417,73.996 152.774,73.996 ; v1(152.452,74.947) 152.452,74.908 152.774,74.586 152.774,73.996 ; v1(152.683,84.499) 152.723,84.499 152.86,84.637 153.422,84.637 153.451,84.665 153.554,84.665 v1(153.582,84.693) ; v1(153.463,75.657) 153.502,75.657 153.577,75.732 C266.1@154.525,75.732 ; v1@153.554,84.699 153.554,84.705 153.969,85.12 153.969,85.647 154.222,85.9 C270.1@154.66,85.9 ; C270.1@154.66,85.854 155.257,85.258 156.418,85.258 C268.1@156.568,85.107 ; C267.1@154.924,74.077 154.804,74.196 153.655,74.196 153.528,74.069 153.278,74.069 153.205,73.996 152.774,73.996
  Bottom Layer_Signals w0.305: C263.2@152.158,78.631 152.161,78.634 152.161,78.748 152.161,78.887 v1(152.179,78.905)
  other v1: 83.611,32.005 82.531,32.164 82.188,32.689 83.043,32.989 82.168,33.506 82.199,34.323 87.002,47.162 87.721,47.576 87.083,47.775 87.667,48.182 87.098,48.536
VDD_NPU_S0: C245.1 C246.1 C247.1 C248.1 C249.2 C250.1 C275.1 C281.1 C515.1 C516.1 R124.1 R309.2 TP51.1 U3.AB21 U3.AB22 U3.AB23 U3.AC22 U3.AC23 U3.AD22 U3.AD23 U3.AE22 U3.AE23 U24.A4 | length 119.1
  Top Layer 1 _Signal w0.254: U3.AB21@155.129,76.628 U3.AB22@155.779,76.628 U3.AB23@156.429,76.628 U3.AE23@156.429,74.678 ; v1(155.437,75.008) 155.448,75.008 155.768,75.328 U3.AD22@155.779,75.328 ; v1(155.476,76.339) 155.504,76.311 155.504,76.271 155.779,75.996 U3.AC22@155.779,75.978 U3.AD22@155.779,75.328 ; U3.AE22@155.779,74.678 U3.AD22@155.779,75.328 ; U24.A4@185.247,38.157 185.325,38.236 186.648,38.236 v1(186.673,38.26) 186.689,38.244 187.281,38.244 R124.1@187.297,38.228
  Top Layer 1 _Signal w0.762: C245.1@157.857,65.941 157.857,65.878 157.876,65.859 157.876,64.207 C246.1@157.966,64.118 157.966,64.019 157.882,63.935 157.882,62.509 TP51.1@157.903,62.488 157.903,61.489 157.897,61.483 157.897,60.79 v1(157.916,60.772) v1(157.916,59.737) v1(157.916,58.719) 157.916,57.604 v1(157.879,57.568) v1(157.879,56.722) ; v1(175.828,24.867) 175.828,24.924 v1(175.328,25.425) 174.891,25.861 v1(174.891,26.083) 174.491,26.483 v1(174.491,26.762) 174.491,26.955 v1(173.947,27.499) 174.398,27.949 v1(174.57,27.949) 174.57,27.935 v1(175.106,27.399) 175.106,27.327 v1(175.714,26.719) 175.714,26.37 176.951,25.133 R309.2@177.201,25.133 177.264,25.133 177.558,24.839 177.558,23.315 179.333,21.541 179.333,21.415 181.465,19.284 C515.1@182.348,19.284
  L5_POWER w0.254: v1(155.437,75.008) 155.437,70.868 155.026,70.457 155.026,70.116 157.841,67.302 157.841,55.317 169.012,44.145 169.012,32.857 177.032,24.837 ; v1(185.759,38.014) 185.798,38.014 186.02,38.236 186.648,38.236 v1(186.673,38.26)
  L5_POWER w0.762: v1(174.57,27.949) 174.57,32.299 178.312,36.042 183.787,36.042 v1(185.759,38.014) v1@185.792,37.982
  Bottom Layer_Signals w0.254: C247.1@155.136,77.092 155.099,77.055 155.292,76.862 155.292,76.523 ; v1(155.437,75.008) 156.347,74.098 156.347,73.214 C249.2@156.452,73.109 ; v1(155.476,76.339) 155.292,76.523 ; v1(156.044,76.918) 156.188,76.775 156.188,76.671 155.807,76.671 155.659,76.523 155.292,76.523 ; C250.1@156.269,75.61 156.235,75.61 156.23,75.614 156.23,76.122 156.201,76.152 156.201,76.671 156.597,76.671 C248.1@156.61,76.686 C248.1@156.61,76.686 ; v1(156.744,75.037) 156.744,75.027 157.343,74.428 C275.1@157.353,74.428
VDD_VDENC_S0: C163.2 C230.2 C231.2 C234.1 C235.1 C236.2 C243.1 C244.1 C282.2 C446.1 R38.1 R290.2 R291.2 TP49.1 TP50.1 U3.R14 U3.T14 U3.U14 U3.V12 U3.V13 U3.V14 U3.W13 U3.W14 U5.24 | length 43.2
  Top Layer 1 _Signal w0.254: U3.V12@149.279,79.228 149.279,79.214 149.546,78.947 v1(149.546,78.932) 149.561,78.932 149.915,78.578 U3.W13@149.929,78.578 ; v1(150.24,79.561) 150.231,79.552 150.231,79.548 149.929,79.246 U3.V13@149.929,79.228 U3.V14@150.579,79.228 ; U3.W14@150.579,78.578 U3.V14@150.579,79.228 ; U3.R14@150.579,81.178 U3.T14@150.579,80.528 U3.U14@150.579,79.878 U3.V14@150.579,79.228
  Top Layer 1 _Signal w0.635: 118.08,71.555 v1(120.137,71.555) 125.511,71.555 TP49.1@125.688,71.377
  Top Layer 1 _Signal w1.016: C446.1@96.775,75.216 99.287,75.216 v1(99.314,75.242)
  L5_POWER w0.635: v1(97.956,75.277) 109.203,75.277 112.925,71.555 118.266,71.555 v1(118.289,71.578)
  Bottom Layer_Signals w0.254: C282.2@148.078,78.105 148.081,78.108 148.081,79.08 C231.2@148.083,79.083 148.083,79.09 148.206,79.213 148.667,79.213 148.948,78.932 v1(149.546,78.932) 149.546,78.893 149.65,78.79 149.65,78.361 C236.2@149.663,78.348 149.654,78.339 149.654,78.068 149.641,78.054 149.655,78.04 149.655,77.446 C230.2@149.757,77.343 ; C244.1@150.185,80.412 149.766,80.412 149.529,80.175 C243.1@149.529,79.542 149.533,79.546 150.225,79.546 v1(150.24,79.561)
  other v1: 98.582,75.251
VDDA_1V2_S0: C557.2 U5.57
VDDH18: C111.1 C112.1 FB2.2 U1.A5 U1.B5 | length 6.9
  Top Layer 1 _Signal w0.381: U1.B5@278.581,78.48 U1.A5@279.381,78.48 ; v1(280.639,79.428) 280.329,79.428 U1.A5@279.381,78.48 ; v1(280.826,78.029) 279.927,78.029 279.475,78.48 U1.A5@279.381,78.48
  Bottom Layer_Signals w0.381: C112.1@279.972,79.494 280.034,79.432 280.636,79.432 v1(280.639,79.428) ; FB2.2@280.088,77.807 280.259,77.636 280.259,76.732 280.259,76.648 C111.1@280.189,76.578 ; FB2.2@280.126,77.769 280.279,77.922 280.72,77.922 v1(280.826,78.029)
VDDH18_PCIE: C113.1 C114.1 FB3.2 U1.T17 | length 5.9
  Top Layer 1 _Signal w0.381: U1.T17@267.381,68.88 267.381,69.059 267.65,69.328 v1(267.672,69.328)
  Bottom Layer_Signals w0.381: C113.1@265.603,69.275 265.991,68.887 266.504,68.887 266.942,69.324 267.669,69.324 v1(267.672,69.328) ; C114.1@267.732,68.493 267.672,68.554 v1(267.672,69.328) ; FB3.2@269.407,70.029 269.407,69.984 269.198,69.776 268.933,69.776 268.722,69.565 267.914,69.565 267.678,69.328 v1(267.672,69.328)
VDDHS: C121.2 C122.1 C123.1 C124.1 C125.1 C126.1 C127.1 C128.1 C129.1 C130.1 C131.1 C134.1 C135.1 FB7.2 U1.G6 U1.G8 U1.G10 U1.G12 U1.G14 U1.H7 U1.H9 U1.H11 U1.H13 U1.H15 | length 35.9
  Top Layer 1 _Signal w0.381: U1.H15@273.781,70.48 U1.G14@274.581,71.28 U1.H13@273.781,72.08 v1(274.201,72.501) ; U1.G12@274.581,72.88 U1.H11@273.781,73.68 U1.G10@274.581,74.48 U1.H9@273.781,75.28 U1.G8@274.581,76.08 ; U1.G6@274.581,77.68 274.577,77.68 v1(274.165,77.268) 274.165,77.264 U1.H7@273.781,76.88 U1.G8@274.581,76.08 ; v1(274.913,75.748) U1.G8@274.581,76.08
  L5_POWER w0.381: v1(274.913,75.748) 277.112,75.748 277.509,76.145 279.708,76.145 v1(280.574,75.279)
  Bottom Layer_Signals w0.381: C124.1@271.572,75.564 272.057,75.564 272.298,75.804 272.298,76.487 273.184,77.373 C121.2@273.184,77.423 ; C134.1@271.723,78.384 272.613,78.384 C135.1@272.664,78.333 272.664,77.992 273.184,77.473 C121.2@273.184,77.423 ; 272.001,75.564 272.369,75.196 272.612,75.196 272.835,74.973 272.786,74.923 C125.1@272.786,74.761 272.742,74.717 272.742,73.755 272.964,73.533 273.069,73.533 273.262,73.725 273.753,73.725 273.92,73.559 C130.1@274.411,73.559 274.201,73.35 274.201,72.495 274.687,72.01 274.687,71.569 274.681,71.562 C122.1@274.681,71.344 273.908,71.344 C123.1@273.873,71.309 273.873,71.161 273.128,70.415 C129.1@272.988,70.415 ; v1(274.165,77.268) 274.16,77.268 274.005,77.423 C121.2@273.184,77.423 ; v1(274.201,72.501) 274.205,72.497 274.805,72.497 274.975,72.326 275.123,72.326 275.193,72.257 C127.1@275.243,72.257 ; v1(274.913,75.748) 274.918,75.748 274.989,75.819 275.513,75.819 275.823,76.129 C128.1@275.823,76.169 ; v1(275.849,69.273) 276.025,69.098 276.025,68.776 276.22,68.58 C131.1@276.377,68.58
  Bottom Layer_Signals w0.508: v1(280.574,75.279) 280.592,75.297 281.427,75.297 281.673,75.051 FB7.2@281.673,74.823
VDDHS_PCIE: C118.1 C119.1 FB5.2 U1.V19 U1.W18 | length 20
  Top Layer 1 _Signal w0.381: U1.W18@264.981,68.08 263.496,69.565 262.676,69.565 262.453,69.342 262.453,66.747 v1(262.451,66.745) 265.067,66.745 265.53,67.207 265.708,67.207 U1.V19@265.781,67.28
  L6_Signals w0.381: v1(262.451,66.745) 262.451,71.104 v1(264.104,72.757)
  Bottom Layer_Signals w0.254: v1(264.104,72.757) 264.144,72.757 264.223,72.837 265.183,72.837 265.483,72.537 265.483,72.488 265.662,72.309 C119.1@265.662,72.299
  Bottom Layer_Signals w0.381: C118.1@265.605,71.246 265.605,71.252 265.743,71.39 265.857,71.505 266.762,71.505 FB5.2@266.771,71.513 ; 265.662,71.471 C119.1@265.662,72.299
VDDHV: C116.1 C117.1 FB4.2 U1.D5 U1.F5 | length 5.9
  Top Layer 1 _Signal w0.254: U1.F5@275.381,78.48 275.402,78.48 275.775,78.854 275.896,78.854 v1(275.924,78.882) 275.927,78.879 276.562,78.879 276.96,78.48 U1.D5@276.981,78.48
  Bottom Layer_Signals w0.254: C116.1@274.348,78.35 274.358,78.36 274.797,78.36 274.889,78.453 275.23,78.453 275.235,78.448 276.027,78.448 276.04,78.461 C117.1@276.04,78.471 276.027,78.484 276.027,78.738 275.924,78.842 v1(275.924,78.882) ; C117.1@275.988,78.418 276.128,78.279 276.128,78.176 276.538,77.765 276.775,77.765 277.164,77.376 FB4.2@277.164,77.334
VDDHV_PCIE: C115.1 C120.1 FB6.2 U1.U17 | length 8.1
  Top Layer 1 _Signal w0.132: v1(265.531,65.227) 265.559,65.227 266.121,65.789 266.121,67.266 266.463,67.608 266.554,67.608 266.896,67.95 266.896,68.565 U1.U17@266.581,68.88
  Bottom Layer_Signals w0.132: v1(265.531,65.227) FB6.2@265.531,66.003
  Bottom Layer_Signals w0.381: C120.1@263.991,65.727 265.031,65.727 ; C115.1@265.051,64.785 265.051,65.605 ; 265.051,65.553 265.405,65.906 265.439,65.906 265.59,66.057 265.781,66.248 FB6.2@265.781,66.293
VDDPLLDDR: C107.1 C108.1 FB1.1 U1.P5 U1.R4 | length 9.4
  Top Layer 1 _Signal w0.381: U1.R4@268.181,79.28 v1(268.575,79.674) ; U1.P5@268.981,78.48 v1(269.366,78.865)
  Bottom Layer_Signals w0.381: C108.1@267.509,80.027 267.858,79.678 268.571,79.678 v1(268.575,79.674) 268.579,79.678 269.224,79.678 C107.1@269.366,79.82 ; v1(269.366,78.865) 269.366,79.678 C107.1@269.366,79.82 ; FB1.1@274.039,80.537 273.987,80.589 272.925,80.589 272.724,80.79 270.188,80.79 269.366,79.968 C107.1@269.366,79.82
VDDQ_DDR_CK: C298.2 C302.2 R265.1 TP57.1 U3.L10 U3.M13 | length 7
  Top Layer 1 _Signal w0.203: U3.L10@147.979,83.778 148.002,83.8 148.002,84.149 v1(148.052,84.199) ; v1(149.675,83.351) 149.691,83.351 149.914,83.128 U3.M13@149.929,83.128
  Top Layer 1 _Signal w0.406: TP57.1@134.858,94.212 134.91,94.212 134.988,94.29 R265.1@136.337,94.29 136.337,95.172 v1(136.426,95.26)
  Bottom Layer_Signals w0.203: C298.2@146.701,85.029 146.739,84.991 146.739,84.981 147.064,84.656 147.507,84.656 C302.2@147.519,84.644 147.529,84.644 147.649,84.524 147.673,84.524 147.998,84.199 v1(148.052,84.199) 148.089,84.161 148.549,84.161 149.22,83.491 149.482,83.491 149.622,83.351 v1(149.675,83.351)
